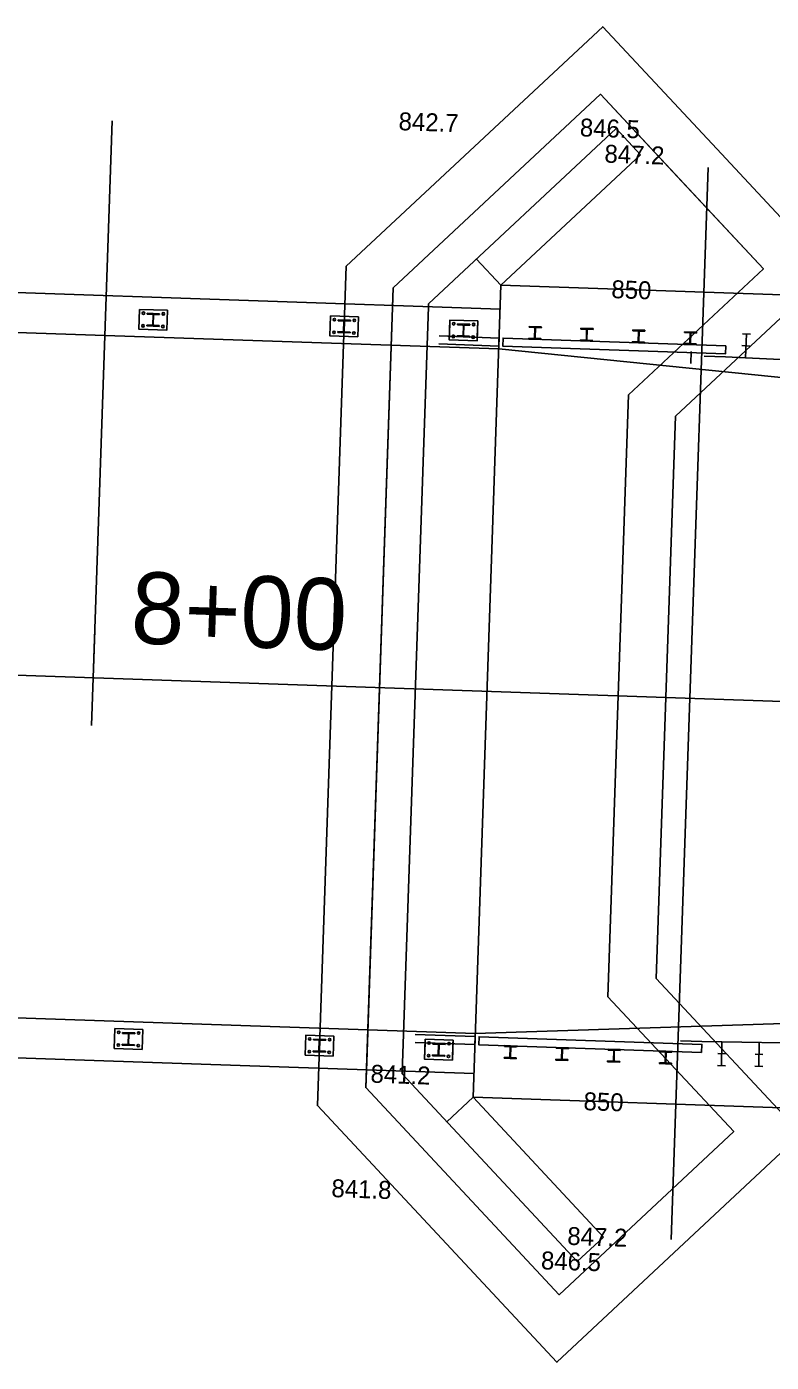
# Model space of a CAD drawing. Extents: x 2191309 to 2193046, y 863659 to 865133.
# Drawn here: x 2191715.3 to 2191746.5, y 865057.5 to 865113.4 of the extents above; entities that cross this region are included whole.
import ezdxf

# ---------------------------------------------------------------- set-up
doc = ezdxf.new("R2010")
doc.units = 0
for name, color, linetype in [('D_Bridge_Abutment', 7, 'Continuous'), ('D_Bridge_Deck', 7, 'Continuous'), ('D_Bridge_Railing', 7, 'Continuous'), ('D_Bridge_Substructure_Hidden', 7, 'Continuous'), ('D_Guardrail_Beam_Lt', 7, 'Continuous'), ('D_Roadway_Centerline', 7, 'Continuous'), ('D_Roadway_Centerline_Text', 7, 'Continuous'), ('D_Roadway_Edge_Shoulder', 7, 'Continuous'), ('D_Roadway_Edge_TW', 7, 'Continuous'), ('JUNK', 7, 'Continuous')]:
    doc.layers.add(name, color=color, linetype=linetype)

msp = doc.modelspace()

# ---------------------------------------------------------------- linework, layer by layer
at = {"layer": 'D_Bridge_Abutment'}
for p, q in [((2191732.116, 865101.799), (2191739.969, 865109.13)), ((2191740.992, 865108.034), (2191739.969, 865109.13)), ((2191735.145, 865102.575), (2191740.992, 865108.034)), ((2191735.145, 865102.575), (2191734.121, 865103.671)), ((2191733.979, 865068.595), (2191735.145, 865102.575)), ((2191732.112, 865101.678), (2191732.116, 865101.799)), ((2191731.026, 865070.03), (2191731.01, 865069.576)), ((2191731.01, 865069.576), (2191738.342, 865061.723)), ((2191732.882, 865067.571), (2191733.979, 865068.595)), ((2191733.979, 865068.595), (2191739.438, 865062.747)), ((2191738.342, 865061.723), (2191739.438, 865062.747))]:
    msp.add_line(p, q, dxfattribs=at)
at = {"layer": 'D_Bridge_Deck'}
for p, q in [((2191698.132, 865102.844), (2191735.111, 865101.575)), ((2191698.075, 865101.179), (2191735.053, 865099.909)), ((2191697.092, 865072.529), (2191734.07, 865071.26)), ((2191697.035, 865070.863), (2191734.013, 865069.594))]:
    msp.add_line(p, q, dxfattribs=at)
at = {"layer": 'D_Bridge_Railing'}
for p, q in [((2191720.341, 865101.404), (2191720.34, 865101.368)), ((2191720.34, 865101.368), (2191720.551, 865101.361)), ((2191720.851, 865101.387), (2191720.341, 865101.404)), ((2191720.581, 865101.329), (2191720.567, 865100.932)), ((2191720.593, 865100.932), (2191720.607, 865101.328)), ((2191720.638, 865101.358), (2191720.85, 865101.35)), ((2191720.85, 865101.35), (2191720.851, 865101.387)), ((2191720.324, 865100.91), (2191720.323, 865100.873)), ((2191720.323, 865100.873), (2191720.833, 865100.856)), ((2191720.535, 865100.903), (2191720.324, 865100.91)), ((2191720.834, 865100.892), (2191720.623, 865100.9)), ((2191720.833, 865100.856), (2191720.834, 865100.892)), ((2191728.336, 865101.13), (2191728.335, 865101.094)), ((2191728.335, 865101.094), (2191728.546, 865101.086)), ((2191728.846, 865101.112), (2191728.336, 865101.13)), ((2191728.576, 865101.054), (2191728.562, 865100.658)), ((2191728.588, 865100.657), (2191728.602, 865101.054)), ((2191728.634, 865101.083), (2191728.845, 865101.076)), ((2191728.845, 865101.076), (2191728.846, 865101.112)), ((2191733.333, 865100.958), (2191733.332, 865100.922)), ((2191733.332, 865100.922), (2191733.543, 865100.915)), ((2191733.843, 865100.941), (2191733.333, 865100.958)), ((2191733.334, 865100.921), (2191733.335, 865100.959)), ((2191733.544, 865100.914), (2191733.334, 865100.921)), ((2191733.335, 865100.959), (2191733.841, 865100.941)), ((2191733.559, 865100.487), (2191733.573, 865100.883)), ((2191733.573, 865100.883), (2191733.559, 865100.486)), ((2191733.585, 865100.486), (2191733.599, 865100.882)), ((2191733.599, 865100.882), (2191733.586, 865100.486)), ((2191733.84, 865100.904), (2191733.63, 865100.911)), ((2191733.631, 865100.912), (2191733.842, 865100.905)), ((2191733.841, 865100.941), (2191733.84, 865100.904)), ((2191733.842, 865100.905), (2191733.843, 865100.941)), ((2191736.332, 865100.818), (2191736.333, 865100.856)), ((2191736.542, 865100.811), (2191736.332, 865100.818)), ((2191736.333, 865100.856), (2191736.84, 865100.839)), ((2191736.557, 865100.384), (2191736.571, 865100.78)), ((2191736.597, 865100.779), (2191736.584, 865100.383)), ((2191736.838, 865100.801), (2191736.628, 865100.808)), ((2191736.84, 865100.839), (2191736.838, 865100.801)), ((2191738.497, 865100.744), (2191738.499, 865100.782)), ((2191738.707, 865100.737), (2191738.497, 865100.744)), ((2191738.499, 865100.782), (2191739.005, 865100.764)), ((2191738.723, 865100.31), (2191738.736, 865100.706)), ((2191738.763, 865100.705), (2191738.749, 865100.309)), ((2191739.004, 865100.726), (2191738.794, 865100.734)), ((2191739.005, 865100.764), (2191739.004, 865100.726)), ((2191740.663, 865100.669), (2191740.664, 865100.707)), ((2191740.873, 865100.662), (2191740.663, 865100.669)), ((2191740.664, 865100.707), (2191741.17, 865100.69)), ((2191741.169, 865100.652), (2191740.959, 865100.659)), ((2191741.17, 865100.69), (2191741.169, 865100.652)), ((2191728.319, 865100.635), (2191728.318, 865100.599)), ((2191728.318, 865100.599), (2191728.828, 865100.582)), ((2191728.53, 865100.628), (2191728.319, 865100.635)), ((2191728.829, 865100.618), (2191728.618, 865100.625)), ((2191728.828, 865100.582), (2191728.829, 865100.618)), ((2191733.316, 865100.464), (2191733.315, 865100.428)), ((2191733.315, 865100.428), (2191733.825, 865100.41)), ((2191733.527, 865100.457), (2191733.316, 865100.464)), ((2191733.317, 865100.427), (2191733.318, 865100.465)), ((2191733.823, 865100.41), (2191733.317, 865100.427)), ((2191733.318, 865100.465), (2191733.528, 865100.458)), ((2191733.614, 865100.455), (2191733.824, 865100.448)), ((2191733.826, 865100.446), (2191733.615, 865100.454)), ((2191733.824, 865100.448), (2191733.823, 865100.41)), ((2191733.825, 865100.41), (2191733.826, 865100.446)), ((2191736.315, 865100.325), (2191736.316, 865100.362)), ((2191736.821, 865100.307), (2191736.315, 865100.325)), ((2191736.316, 865100.362), (2191736.526, 865100.355)), ((2191736.613, 865100.352), (2191736.823, 865100.345)), ((2191736.823, 865100.345), (2191736.821, 865100.307)), ((2191738.48, 865100.25), (2191738.482, 865100.288)), ((2191738.987, 865100.233), (2191738.48, 865100.25)), ((2191738.482, 865100.288), (2191738.692, 865100.281)), ((2191738.778, 865100.278), (2191738.988, 865100.271)), ((2191738.988, 865100.271), (2191738.987, 865100.233)), ((2191740.646, 865100.176), (2191740.647, 865100.214)), ((2191741.152, 865100.159), (2191740.646, 865100.176)), ((2191740.647, 865100.214), (2191740.857, 865100.207)), ((2191740.888, 865100.235), (2191740.902, 865100.631)), ((2191740.928, 865100.63), (2191740.915, 865100.234)), ((2191740.943, 865100.204), (2191741.153, 865100.196)), ((2191741.153, 865100.196), (2191741.152, 865100.159)), ((2191742.811, 865100.102), (2191742.812, 865100.14)), ((2191743.318, 865100.084), (2191742.811, 865100.102)), ((2191742.812, 865100.14), (2191743.023, 865100.132)), ((2191742.828, 865100.595), (2191742.829, 865100.633)), ((2191743.038, 865100.588), (2191742.828, 865100.595)), ((2191742.829, 865100.633), (2191743.336, 865100.616)), ((2191743.053, 865100.161), (2191743.067, 865100.557)), ((2191743.094, 865100.556), (2191743.08, 865100.16)), ((2191743.109, 865100.129), (2191743.319, 865100.122)), ((2191743.334, 865100.578), (2191743.124, 865100.585)), ((2191743.319, 865100.122), (2191743.318, 865100.084)), ((2191743.336, 865100.616), (2191743.334, 865100.578)), ((2191719.307, 865071.272), (2191719.308, 865071.308)), ((2191719.518, 865071.264), (2191719.307, 865071.272)), ((2191719.308, 865071.308), (2191719.818, 865071.29)), ((2191719.534, 865070.836), (2191719.548, 865071.232)), ((2191719.574, 865071.232), (2191719.56, 865070.835)), ((2191719.817, 865071.254), (2191719.605, 865071.261)), ((2191719.818, 865071.29), (2191719.817, 865071.254)), ((2191719.29, 865070.777), (2191719.291, 865070.813)), ((2191719.8, 865070.76), (2191719.29, 865070.777)), ((2191719.291, 865070.813), (2191719.502, 865070.806)), ((2191719.59, 865070.803), (2191719.801, 865070.796)), ((2191719.801, 865070.796), (2191719.8, 865070.76)), ((2191727.285, 865070.503), (2191727.286, 865070.539)), ((2191727.795, 865070.485), (2191727.285, 865070.503)), ((2191727.286, 865070.539), (2191727.497, 865070.532)), ((2191727.302, 865070.997), (2191727.303, 865071.034)), ((2191727.513, 865070.99), (2191727.302, 865070.997)), ((2191727.303, 865071.034), (2191727.813, 865071.016)), ((2191727.529, 865070.562), (2191727.543, 865070.958)), ((2191727.569, 865070.957), (2191727.555, 865070.561)), ((2191727.585, 865070.529), (2191727.796, 865070.522)), ((2191727.812, 865070.98), (2191727.601, 865070.987)), ((2191727.796, 865070.522), (2191727.795, 865070.485)), ((2191727.813, 865071.016), (2191727.812, 865070.98)), ((2191732.299, 865070.826), (2191732.3, 865070.862)), ((2191732.51, 865070.818), (2191732.299, 865070.826)), ((2191732.3, 865070.862), (2191732.81, 865070.845)), ((2191732.302, 865070.862), (2191732.301, 865070.824)), ((2191732.301, 865070.824), (2191732.511, 865070.817)), ((2191732.808, 865070.845), (2191732.302, 865070.862)), ((2191732.54, 865070.786), (2191732.526, 865070.39)), ((2191732.526, 865070.39), (2191732.54, 865070.786)), ((2191732.566, 865070.786), (2191732.552, 865070.389)), ((2191732.553, 865070.389), (2191732.566, 865070.785)), ((2191732.597, 865070.814), (2191732.807, 865070.807)), ((2191732.809, 865070.808), (2191732.598, 865070.815)), ((2191732.807, 865070.807), (2191732.808, 865070.845)), ((2191732.81, 865070.845), (2191732.809, 865070.808)), ((2191735.3, 865070.759), (2191735.299, 865070.721)), ((2191735.299, 865070.721), (2191735.509, 865070.714)), ((2191735.807, 865070.742), (2191735.3, 865070.759)), ((2191735.538, 865070.683), (2191735.524, 865070.287)), ((2191735.551, 865070.286), (2191735.564, 865070.682)), ((2191735.595, 865070.711), (2191735.805, 865070.704)), ((2191735.805, 865070.704), (2191735.807, 865070.742)), ((2191737.466, 865070.685), (2191737.464, 865070.647)), ((2191737.464, 865070.647), (2191737.674, 865070.64)), ((2191737.972, 865070.667), (2191737.466, 865070.685)), ((2191737.703, 865070.609), (2191737.69, 865070.213)), ((2191737.716, 865070.212), (2191737.73, 865070.608)), ((2191737.761, 865070.637), (2191737.971, 865070.629)), ((2191737.971, 865070.629), (2191737.972, 865070.667)), ((2191739.631, 865070.61), (2191739.63, 865070.573)), ((2191739.63, 865070.573), (2191739.84, 865070.565)), ((2191740.137, 865070.593), (2191739.631, 865070.61)), ((2191739.869, 865070.535), (2191739.855, 865070.139)), ((2191739.882, 865070.138), (2191739.895, 865070.534)), ((2191739.926, 865070.562), (2191740.136, 865070.555)), ((2191740.136, 865070.555), (2191740.137, 865070.593)), ((2191741.796, 865070.536), (2191741.795, 865070.498)), ((2191741.795, 865070.498), (2191742.005, 865070.491)), ((2191742.303, 865070.519), (2191741.796, 865070.536)), ((2191742.091, 865070.488), (2191742.302, 865070.481)), ((2191742.302, 865070.481), (2191742.303, 865070.519)), ((2191732.282, 865070.331), (2191732.283, 865070.368)), ((2191732.792, 865070.314), (2191732.282, 865070.331)), ((2191732.283, 865070.368), (2191732.494, 865070.36)), ((2191732.285, 865070.369), (2191732.284, 865070.331)), ((2191732.284, 865070.331), (2191732.79, 865070.313)), ((2191732.495, 865070.361), (2191732.285, 865070.369)), ((2191732.791, 865070.351), (2191732.581, 865070.358)), ((2191732.582, 865070.357), (2191732.793, 865070.35)), ((2191732.79, 865070.313), (2191732.791, 865070.351)), ((2191732.793, 865070.35), (2191732.792, 865070.314)), ((2191735.283, 865070.266), (2191735.282, 865070.228)), ((2191735.282, 865070.228), (2191735.788, 865070.21)), ((2191735.493, 865070.258), (2191735.283, 865070.266)), ((2191735.79, 865070.248), (2191735.58, 865070.255)), ((2191735.788, 865070.21), (2191735.79, 865070.248)), ((2191737.449, 865070.191), (2191737.447, 865070.153)), ((2191737.447, 865070.153), (2191737.954, 865070.136)), ((2191737.659, 865070.184), (2191737.449, 865070.191)), ((2191737.955, 865070.174), (2191737.745, 865070.181)), ((2191737.954, 865070.136), (2191737.955, 865070.174)), ((2191739.614, 865070.117), (2191739.613, 865070.079)), ((2191739.613, 865070.079), (2191740.119, 865070.062)), ((2191739.824, 865070.11), (2191739.614, 865070.117)), ((2191740.12, 865070.1), (2191739.91, 865070.107)), ((2191740.119, 865070.062), (2191740.12, 865070.1)), ((2191741.78, 865070.043), (2191741.778, 865070.005)), ((2191741.778, 865070.005), (2191742.285, 865069.987)), ((2191741.99, 865070.035), (2191741.78, 865070.043)), ((2191742.034, 865070.46), (2191742.02, 865070.064)), ((2191742.047, 865070.063), (2191742.061, 865070.459)), ((2191742.286, 865070.025), (2191742.076, 865070.032)), ((2191742.285, 865069.987), (2191742.286, 865070.025))]:
    msp.add_line(p, q, dxfattribs=at)
for points in [[(2191720.018, 865101.567), (2191721.184, 865101.527), (2191721.155, 865100.694), (2191719.989, 865100.734)], [(2191728.013, 865101.292), (2191729.179, 865101.252), (2191729.151, 865100.419), (2191727.985, 865100.459)], [(2191733.01, 865101.121), (2191734.176, 865101.081), (2191734.148, 865100.248), (2191732.982, 865100.288)], [(2191718.956, 865070.637), (2191720.122, 865070.597), (2191720.151, 865071.43), (2191718.985, 865071.47)], [(2191726.952, 865070.363), (2191728.118, 865070.323), (2191728.146, 865071.156), (2191726.98, 865071.196)], [(2191731.949, 865070.191), (2191733.115, 865070.151), (2191733.143, 865070.984), (2191731.977, 865071.024)]]:
    msp.add_lwpolyline(points, close=True, dxfattribs=at)
for points in [[(2191734.153, 865100.399), (2191734.176, 865101.081), (2191733.01, 865101.121), (2191732.987, 865100.439)], [(2191732.565, 865100.453), (2191735.069, 865100.367), (2191735.058, 865100.034), (2191732.553, 865100.12)], [(2191732.987, 865100.439), (2191732.982, 865100.288), (2191734.148, 865100.248), (2191734.153, 865100.399)], [(2191744.563, 865100.041), (2191735.236, 865100.362), (2191735.224, 865100.028), (2191744.552, 865099.708), (2191744.563, 865100.041)], [(2191731.55, 865070.888), (2191734.054, 865070.802), (2191734.066, 865071.135), (2191731.561, 865071.221)], [(2191743.549, 865070.476), (2191734.221, 865070.796), (2191734.232, 865071.129), (2191743.56, 865070.809), (2191743.549, 865070.476)], [(2191733.138, 865070.833), (2191733.115, 865070.151), (2191731.949, 865070.191), (2191731.972, 865070.873)], [(2191731.972, 865070.873), (2191731.977, 865071.024), (2191733.143, 865070.984), (2191733.138, 865070.833)]]:
    msp.add_lwpolyline(points, dxfattribs=at)
for centre in [(2191720.179, 865101.41), (2191721.012, 865101.381), (2191720.161, 865100.879), (2191720.994, 865100.85), (2191728.156, 865100.605), (2191728.175, 865101.136), (2191729.008, 865101.107), (2191733.172, 865100.964), (2191733.172, 865100.964), (2191734.005, 865100.935), (2191734.005, 865100.935), (2191728.989, 865100.576), (2191733.154, 865100.433), (2191733.986, 865100.404), (2191719.146, 865071.314), (2191719.979, 865071.285), (2191727.142, 865071.039), (2191727.975, 865071.011), (2191719.128, 865070.783), (2191719.961, 865070.754), (2191727.124, 865070.508), (2191727.956, 865070.48), (2191732.139, 865070.868), (2191732.972, 865070.839), (2191732.121, 865070.337), (2191732.121, 865070.337), (2191732.953, 865070.308), (2191732.953, 865070.308)]:
    msp.add_circle(centre, 0.0521, dxfattribs=at)
for centre, radius, start, end in [((2191720.55, 865101.33), 0.0308, 358.0343, 88.0343), ((2191720.637, 865101.327), 0.0308, 88.0343, 178.0343), ((2191720.536, 865100.933), 0.0308, 268.0343, 358.0343), ((2191720.624, 865100.93), 0.0308, 178.0343, 268.0343), ((2191728.531, 865100.659), 0.0308, 268.0343, 358.0343), ((2191728.545, 865101.055), 0.0308, 358.0343, 88.0343), ((2191728.619, 865100.656), 0.0308, 178.0343, 268.0343), ((2191728.633, 865101.052), 0.0308, 88.0343, 178.0343), ((2191733.542, 865100.884), 0.0308, 358.0343, 88.0343), ((2191733.543, 865100.884), 0.0298, 358.0343, 88.0343), ((2191733.63, 865100.881), 0.0308, 88.0343, 178.0343), ((2191733.629, 865100.881), 0.0298, 88.0343, 178.0343), ((2191736.541, 865100.781), 0.0298, 358.0343, 88.0343), ((2191736.627, 865100.778), 0.0298, 88.0343, 178.0343), ((2191738.706, 865100.707), 0.0298, 358.0343, 88.0343), ((2191738.793, 865100.704), 0.0298, 88.0343, 178.0343), ((2191740.872, 865100.632), 0.0298, 358.0343, 88.0343), ((2191740.958, 865100.629), 0.0298, 88.0343, 178.0343), ((2191733.528, 865100.488), 0.0308, 268.0343, 358.0343), ((2191733.529, 865100.488), 0.0298, 268.0343, 358.0343), ((2191733.616, 865100.485), 0.0308, 178.0343, 268.0343), ((2191733.615, 865100.485), 0.0298, 178.0343, 268.0343), ((2191736.527, 865100.385), 0.0298, 268.0343, 358.0343), ((2191736.614, 865100.382), 0.0298, 178.0343, 268.0343), ((2191738.693, 865100.311), 0.0298, 268.0343, 358.0343), ((2191738.779, 865100.308), 0.0298, 178.0343, 268.0343), ((2191740.858, 865100.236), 0.0298, 268.0343, 358.0343), ((2191740.944, 865100.233), 0.0298, 178.0343, 268.0343), ((2191743.024, 865100.162), 0.0298, 268.0343, 358.0343), ((2191743.037, 865100.558), 0.0298, 358.0343, 88.0343), ((2191743.11, 865100.159), 0.0298, 178.0343, 268.0343), ((2191743.123, 865100.555), 0.0298, 88.0343, 178.0343), ((2191719.517, 865071.233), 0.0308, 358.0343, 88.0343), ((2191719.604, 865071.23), 0.0308, 88.0343, 178.0343), ((2191719.503, 865070.837), 0.0308, 268.0343, 358.0343), ((2191719.591, 865070.834), 0.0308, 178.0343, 268.0343), ((2191727.498, 865070.563), 0.0308, 268.0343, 358.0343), ((2191727.512, 865070.959), 0.0308, 358.0343, 88.0343), ((2191727.586, 865070.56), 0.0308, 178.0343, 268.0343), ((2191727.6, 865070.956), 0.0308, 88.0343, 178.0343), ((2191732.509, 865070.788), 0.0308, 358.0343, 88.0343), ((2191732.51, 865070.787), 0.0298, 358.0343, 88.0343), ((2191732.597, 865070.785), 0.0308, 88.0343, 178.0343), ((2191732.596, 865070.784), 0.0298, 88.0343, 178.0343), ((2191735.508, 865070.684), 0.0298, 358.0343, 88.0343), ((2191735.594, 865070.681), 0.0298, 88.0343, 178.0343), ((2191737.673, 865070.61), 0.0298, 358.0343, 88.0343), ((2191737.76, 865070.607), 0.0298, 88.0343, 178.0343), ((2191739.839, 865070.536), 0.0298, 358.0343, 88.0343), ((2191739.925, 865070.533), 0.0298, 88.0343, 178.0343), ((2191742.004, 865070.461), 0.0298, 358.0343, 88.0343), ((2191742.09, 865070.458), 0.0298, 88.0343, 178.0343), ((2191732.495, 865070.391), 0.0308, 268.0343, 358.0343), ((2191732.496, 865070.391), 0.0298, 268.0343, 358.0343), ((2191732.583, 865070.388), 0.0308, 178.0343, 268.0343), ((2191732.582, 865070.388), 0.0298, 178.0343, 268.0343), ((2191735.494, 865070.288), 0.0298, 268.0343, 358.0343), ((2191735.581, 865070.285), 0.0298, 178.0343, 268.0343), ((2191737.66, 865070.214), 0.0298, 268.0343, 358.0343), ((2191737.746, 865070.211), 0.0298, 178.0343, 268.0343), ((2191739.825, 865070.14), 0.0298, 268.0343, 358.0343), ((2191739.911, 865070.137), 0.0298, 178.0343, 268.0343), ((2191741.991, 865070.065), 0.0298, 268.0343, 358.0343), ((2191742.077, 865070.062), 0.0298, 178.0343, 268.0343)]:
    msp.add_arc(centre, radius, start, end, dxfattribs=at)
at = {"layer": 'D_Bridge_Substructure_Hidden'}
for p, q in [((2191730.639, 865102.472), (2191739.311, 865110.568)), ((2191746.135, 865103.259), (2191739.311, 865110.568)), ((2191740.491, 865097.989), (2191746.135, 865103.259)), ((2191729.527, 865070.081), (2191730.639, 865102.472)), ((2191731.026, 865070.03), (2191732.112, 865101.678)), ((2191739.626, 865072.803), (2191740.491, 865097.989)), ((2191739.626, 865072.803), (2191744.896, 865067.159)), ((2191729.49, 865069.006), (2191729.527, 865070.081)), ((2191729.49, 865069.006), (2191737.586, 865060.334)), ((2191737.586, 865060.334), (2191744.896, 865067.159))]:
    msp.add_line(p, q, dxfattribs=at)
at = {"layer": 'D_Guardrail_Beam_Lt'}
for p, q in [((2191745.598, 865100.531), (2191745.265, 865100.548)), ((2191745.38, 865099.541), (2191745.431, 865100.54)), ((2191744.548, 865099.584), (2191743.652, 865099.614)), ((2191745.38, 865099.541), (2191744.548, 865099.584)), ((2191745.572, 865100.032), (2191745.239, 865100.049)), ((2191757.864, 865098.9), (2191745.38, 865099.541)), ((2191743.564, 865070.934), (2191742.669, 865070.965)), ((2191744.398, 865070.919), (2191743.564, 865070.934)), ((2191744.398, 865070.919), (2191744.38, 865069.92)), ((2191756.896, 865070.703), (2191744.398, 865070.919)), ((2191745.96, 865070.892), (2191745.943, 865069.893)), ((2191744.547, 865069.917), (2191744.214, 865069.922)), ((2191744.556, 865070.417), (2191744.222, 865070.422)), ((2191746.118, 865070.39), (2191745.785, 865070.395)), ((2191746.109, 865069.89), (2191745.776, 865069.895))]:
    msp.add_line(p, q, dxfattribs=at)
for centre, start, end in [((2191733.154, 865100.433), 358.0343, 178.0343), ((2191733.154, 865100.433), 178.0343, 358.0343), ((2191733.986, 865100.404), 358.0343, 178.0343), ((2191733.986, 865100.404), 178.0343, 358.0343), ((2191732.139, 865070.868), 358.0343, 178.0343), ((2191732.139, 865070.868), 178.0343, 358.0343), ((2191732.972, 865070.839), 358.0343, 178.0343), ((2191732.972, 865070.839), 178.0343, 358.0343)]:
    msp.add_arc(centre, 0.0521, start, end, dxfattribs=at)
at = {"layer": 'D_Roadway_Centerline'}
msp.add_line((2191489.641, 865093.991), (2191792.637, 865083.591), dxfattribs=at)
at = {"layer": 'D_Roadway_Centerline_Text'}
msp.add_lwpolyline([(2191718.14, 865088.149), (2191718.003, 865084.152)], dxfattribs=at)
at = {"layer": 'D_Roadway_Edge_Shoulder'}
for p, q in [((2191735.145, 865102.575), (2191793.152, 865100.584)), ((2191733.979, 865068.595), (2191784.928, 865066.846))]:
    msp.add_line(p, q, dxfattribs=at)
at = {"layer": 'D_Roadway_Edge_TW'}
for points in [[(2191735.053, 865099.909), (2191784.798, 865094.867), (2191792.961, 865094.587)], [(2191734.07, 865071.26), (2191784.044, 865072.88), (2191792.314, 865072.596)]]:
    msp.add_lwpolyline(points, dxfattribs=at)
at = {"layer": 'JUNK'}
for p, q in [((2191718.071, 865086.151), (2191718.872, 865109.462)), ((2191743.057, 865085.293), (2191743.819, 865107.51)), ((2191743.1, 865099.3), (2191743.117, 865099.799)), ((2191742.28, 865062.649), (2191743.057, 865085.293))]:
    msp.add_line(p, q, dxfattribs=at)
for points in [[(2191744.185, 865108.278), (2191739.408, 865113.395), (2191728.668, 865103.368), (2191727.463, 865068.247), (2191737.489, 865057.507), (2191747.723, 865067.062), (2191741.653, 865073.562), (2191742.461, 865097.092), (2191748.962, 865103.162), (2191744.185, 865108.278)], [(2191742.723, 865106.913), (2191739.311, 865110.568), (2191730.639, 865102.472), (2191729.49, 865069.006), (2191737.586, 865060.334), (2191744.896, 865067.159), (2191739.626, 865072.803), (2191740.491, 865097.989), (2191746.135, 865103.259), (2191742.723, 865106.913)]]:
    msp.add_lwpolyline(points, dxfattribs=at)

# ---------------------------------------------------------------- texts
at = {"layer": 'D_Roadway_Centerline_Text'}
msp.add_text('8+00', height=3, rotation=358.0343, dxfattribs=at).set_placement((2191719.622, 865087.598))
at = {"layer": 'JUNK'}
for s, p in [('842.7', (2191730.853, 865109.068)), ('846.5', (2191738.442, 865108.808)), ('847.2', (2191739.472, 865107.711)), ('850', (2191739.762, 865102.041)), ('841.2', (2191729.678, 865069.211)), ('850', (2191738.596, 865068.061)), ('841.8', (2191728.041, 865064.422)), ('847.2', (2191737.918, 865062.424)), ('846.5', (2191736.815, 865061.401))]:
    msp.add_text(s, height=0.75, rotation=358.0343, dxfattribs=at).set_placement(p)

doc.saveas('drawing.dxf')
